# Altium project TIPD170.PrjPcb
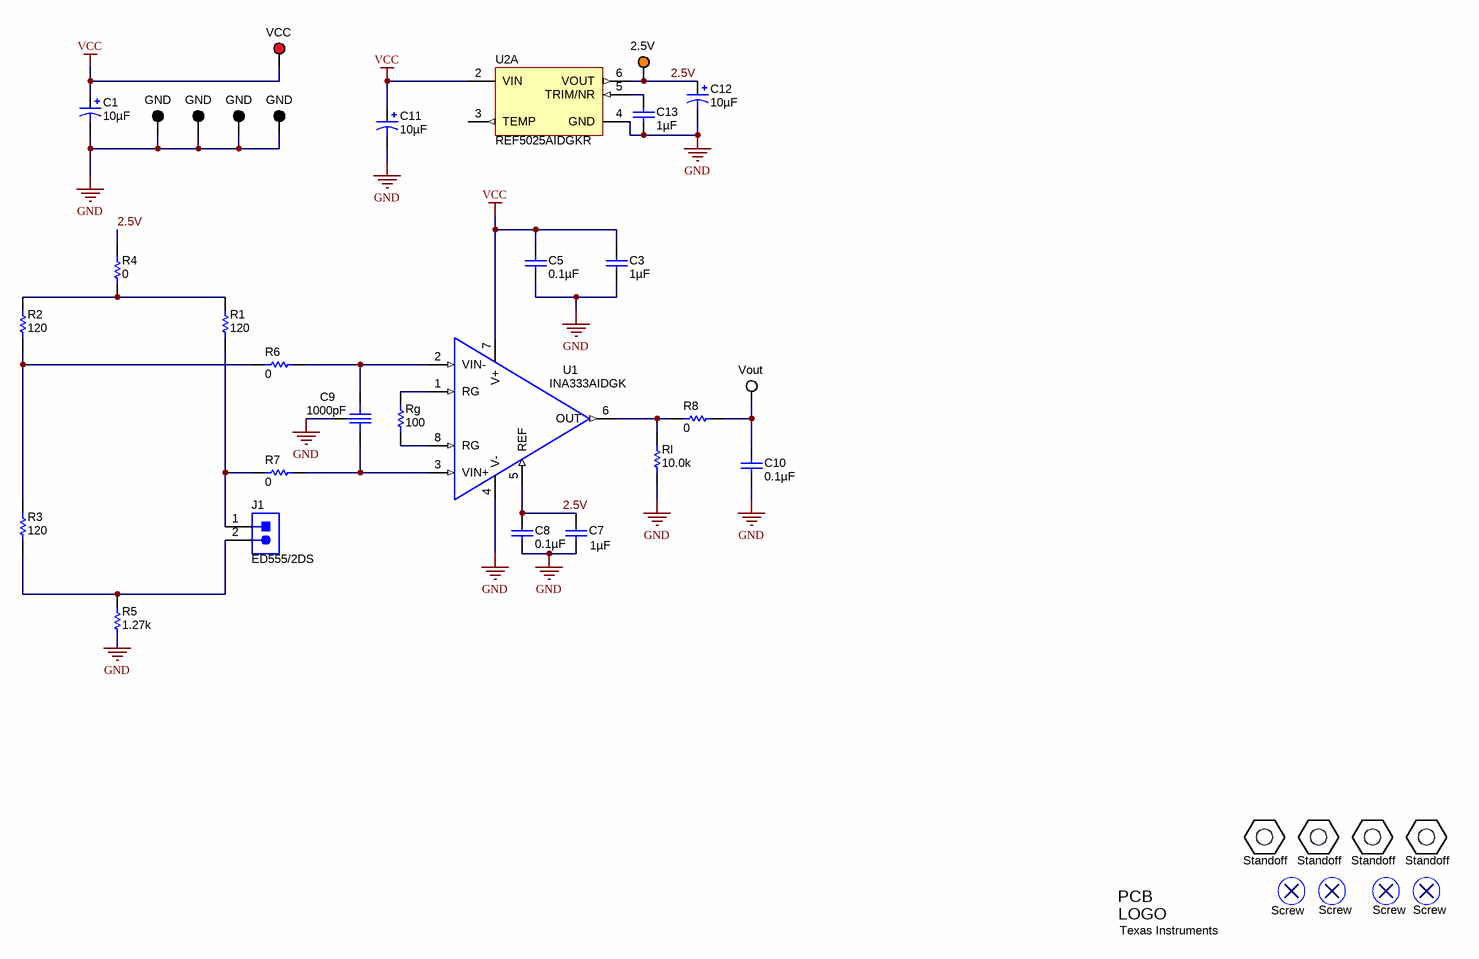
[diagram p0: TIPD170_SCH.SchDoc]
CopyrightYear: 2015; PRJ_Customer: TI Precision Designs; PRJ_Title: Strain Gauge in a Bridge Configuration Reference Design; SCH_Rev: 2; TechSupport: http://www.ti.com/support
1 sheet, 39 parts. Net scope: global (net labels, ports and power ports of the same name join across sheets).
Board file: TIPD170_PCB.PcbDoc

## Sheet TIPD170_SCH.SchDoc: TIPD170
size B; Date: Not shown in title block; ApprovedBy: Not shown in title block; CheckedBy: Not shown in title block; Author: Not shown in title block; CompanyName: Not shown in title block; DrawnBy: Not shown in title block; Engineer: Not shown in title block; Organization: Not shown in title block; Address1: Not shown in title block; Address2: Not shown in title block; Address3: Not shown in title block; Address4: Not shown in title block; DocumentNumber: 1; Revision: Use project parameter SCH_Rev; SheetNumber: 1; SheetTotal: 1; PageSetup: Record=PageOptions¦CenterHorizontal=True¦CenterVertical=True¦PrintScale=0.72¦XCorrection=1.00¦YCorrection=1.00¦PrintKind=0¦BorderSize=5000000¦LeftOffset=0¦BottomOffset=0¦Orientation=2¦PaperLength=1000¦PaperWidth=1000¦Scale=100¦PaperSource=15¦PrintQuality=600¦MediaType=1¦DitherType=10¦PaperKind=Letter¦PrintScaleMode=1

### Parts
C1  ValueDisplayed: 10µF  [3528-21]  (hidden comment: TPSB106M020R1000)
C3  ValueDisplayed: 1µF  [0603]  (hidden comment: GRM188R71E105KA12D)
C5  ValueDisplayed: 0.1µF  [0603]  (hidden comment: 0603YC104JAT2A)
C7  ValueDisplayed: 1µF  [0603]  (hidden comment: GRM188R71E105KA12D)
C8  ValueDisplayed: 0.1µF  [0603]  (hidden comment: 0603YC104JAT2A)
C9  ValueDisplayed: 1000pF  [X2Y_0603]  (hidden comment: CX0603MRX7R0BB102)
C10  ValueDisplayed: 0.1µF  [0603]  (hidden comment: 0603YC104JAT2A)
C11  ValueDisplayed: 10µF  [3528-21]  (hidden comment: TPSB106M020R1000)
C12  ValueDisplayed: 10µF  [3528-21]  (hidden comment: TPSB106M020R1000)
C13  ValueDisplayed: 1µF  [0603]  (hidden comment: GRM188R71E105KA12D)
J1  ED555/2DS  [TERM_BLK_ED555-2DS]
Logo1  Texas Instruments  [TI_Symbol_Overlay_Small]  (no BOM)
R1  ValueDisplayed: 120  [0603]  (hidden comment: RG1608P-121-B-T5)
R2  ValueDisplayed: 120  [0603]  (hidden comment: RG1608P-121-B-T5)
R3  ValueDisplayed: 120  [0603]  (hidden comment: RG1608P-121-B-T5)
R4  ValueDisplayed: 0  [0603]  (hidden comment: CRCW06030000Z0EA)
R5  ValueDisplayed: 1.27k  [0603]  (hidden comment: CRCW06031K27FKEA)
R6  ValueDisplayed: 0  [0603]  (hidden comment: CRCW06030000Z0EA)
R7  ValueDisplayed: 0  [0603]  (hidden comment: CRCW06030000Z0EA)
R8  ValueDisplayed: 0  [0603]  (hidden comment: CRCW06030000Z0EA)
Rg  value 100  [0603]  (hidden comment: RC0603FR-07100RL)
Rl  value 10.0k  [0603]  (hidden comment: CRCW060310K0FKEA)
TP1  VCC  [Keystone5005]
TP2  GND  [Keystone5006]
TP4  GND  [Keystone5006]
TP5  GND  [Keystone5006]
TP6  GND  [Keystone5006]
TP7  2.5V  [Keystone5008]
TP8  Vout  [Keystone5007]
U1  INA333AIDGK  [DGK0008A_N]
U2  REF5025AIDGKR  [DGK0008A_N]  (part A of 2)
U90  Standoff  [STANDOFF HEX 4-40THR ALUM 1"L]
U91  Standoff  [STANDOFF HEX 4-40THR ALUM 1"L]
U92  Standoff  [STANDOFF HEX 4-40THR ALUM 1"L]
U93  Standoff  [STANDOFF HEX 4-40THR ALUM 1"L]
U94  Screw  (mechanical)
U95  Screw  (mechanical)
U96  Screw  (mechanical)
U97  Screw  (mechanical)

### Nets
GND: C1.2(-) C3.2 C5.2 C7.2 C8.2 C9.3 C10.2 C11.2(-) C12.2(-) C13.2 R5.1 Rl.1 TP2.1 TP4.1 TP5.1 TP6.1 U1.4(V-) U2.4(GND)
VCC: C1.1(+) C3.1 C5.1 C11.1(+) TP1.1 U1.7(V+) U2.2(VIN)
2.5V: C7.1 C8.1 C12.1(+) R4.2 TP7.1 U1.5(REF) U2.6(VOUT)
NetC9_1: C9.1 R6.1 U1.2(VIN-)
NetC9_2: C9.2 R7.1 U1.3(VIN+)
NetC10_1: C10.1 R8.2 TP8.1
NetC13_1: C13.1 U2.5(TRIM/NR)
NetJ1_1: J1.1 R1.1 R7.2
NetJ1_2: J1.2 R3.1 R5.2
NetR1_2: R1.2 R2.2 R4.1
NetR2_1: R2.1 R3.2 R6.2
NetR8_1: R8.1 Rl.2 U1.6(OUT)
NetRg_1: Rg.1 U1.8(RG)
NetRg_2: Rg.2 U1.1(RG)

Not connected (* = marked no-connect by the designer): U2 3(TEMP)

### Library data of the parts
C1 C11 C12 = TPSB106M020R1000: CAP, TANT, 10uF, 20V, +/-20%, 1 ohm, 3528-21 SMD; Manufacturer: AVX; Polarized: Y; CompType: Capacitor; U/M: EA; Cap_F: 0.00001; Tolerance_%: 20; Value1: 1 ohm; ESR_Ohm: 1; IRMS_A: 0.262; TaMin_C: -55; TaMax_C: 125; Cap_Case: B
C3 C7 C13 = GRM188R71E105KA12D: CAP, CERM, 1uF, 25V, +/-10%, X7R, 0603; Manufacturer: MuRata; Polarized: N; CompType: Capacitor; U/M: EA; Cap_F: 0.000001; Tolerance_%: 10; Value1: Unknown; VDC_V: 25; TaMin_C: -55; TaMax_C: 125
C5 C8 C10 = 0603YC104JAT2A: CAP, CERM, 0.1uF, 16V, +/-5%, X7R, 0603; Manufacturer: AVX; Polarized: N; CompType: Capacitor; U/M: EA; Cap_F: 0.0000001; Tolerance_%: 5; ESR_Ohm: 0.039; Value1: 0.039 ohm; VDC_V: 16; TaMin_C: -55; TaMax_C: 125
C9 = CX0603MRX7R0BB102: CAP, CERM, 1000 pF, 100 V, +/- 20%, X7R, 0603; Manufacturer: Yageo America; SymbolCreator: a0411947; CompType: Capacitor; U/M: EA; Cap_F: 0.000000001; Value: 1000pF; Tolerance_%: 20; Value1: Unknown; VDC_V: 100; Value2: 100V; TaMin_C: -55; TaMax_C: 125; Polarized: N; Cap_Case: 0603
J1 = ED555/2DS: Terminal Block, 6A, 3.5mm Pitch, 2-Pos, TH; Manufacturer: On-Shore Technology; SymbolCreator: a0412235; CompType: Connector; U/M: EA
Logo1 = TI_Logo: Texas Instrument Corporate Signature; SymbolCreator: codlsc
R1-R3 = RG1608P-121-B-T5: RES, 120, 0.1%, 0.1 W, 0603; Manufacturer: Susumu Co Ltd; CompType: Resistor; Value: 120; Value_Code: 120R; Tolerance_%: 0.1; Value2: 0.1W; VDC_V: 75; TempCo: 25 ppm/C; EIA_Code: E192; U/M: EA
R4 R6-R8 = CRCW06030000Z0EA: RES, 0, 5%, 0.1 W, 0603; Manufacturer: Vishay-Dale; CompType: Resistor; Value: 0; Value_Code: 0000; Tolerance_%: 5; Power_W: 0.1; Value2: 0.1W; VDC_V: 75; TempCo: 200 ppm/C; EIA_Code: E24; U/M: EA; AEC Category: Q200
R5 = CRCW06031K27FKEA: RES, 1.27 k, 1%, 0.1 W, 0603; Manufacturer: Vishay-Dale; CompType: Resistor; Value: 1.27k; Res_ohm: 1270; Value_Code: 1k27; Tolerance_%: 1; Power_W: 0.1; Value2: 0.1W; VDC_V: 75; TempCo: 100 ppm/C; EIA_Code: E96; U/M: EA; AEC Category: Q200
Rg = RC0603FR-07100RL: RES, 100 ohm, 1%, 0.1W, 0603; Manufacturer: Yageo America; CompType: Resistor; Value_Code: 100R; Tolerance_%: 1; Power_W: 0.1; VDC_V: 150; TempCo: 200 ppm/C; EIA_Code: E96; U/M: EA
Rl = CRCW060310K0FKEA: RES, 10.0k ohm, 1%, 0.1W, 0603; Manufacturer: Vishay-Dale; CompType: Resistor; Res_ohm: 10000; Value_Code: 10k0; Tolerance_%: 1; Power_W: 0.1; VDC_V: 75; TempCo: 100 ppm/C; EIA_Code: E96; U/M: EA
TP1 = 5005: Test Point, TH, Compact, Red; Manufacturer: Keystone; Alternate Manufacturer: Any; Alternate PartNumber: Equivalent; CompType: Test Point Loop; U/M: EA
TP2 TP4-TP6 = 5006: Test Point, TH, Compact, Black; Manufacturer: Keystone; Alternate Manufacturer: Any; Alternate PartNumber: Equivalent; CompType: Test Point Loop; U/M: EA
TP7 = 5008: Test Point, Compact, Orange, TH; Manufacturer: Keystone; CompType: Test Point Loop; U/M: EA
TP8 = 5007: Test Point, Compact, White, TH; Manufacturer: Keystone; CompType: Test Point Loop; U/M: EA
U1 = INA333AIDGK: Micro-Power (50mA), Zerø-Drift, Rail-to-Rail Out Instrumentation Amplifier; Manufacturer: Texas Instruments; SymbolCreator: a0799628; CompType: IC; U/M: EA
U2 = REF5025AIDGKR: Low Noise, Very Low Drift, Precision Voltage Reference, -40 to 125 degC, 8-pin MSOP(DGK), Green (RoHS & no Sb/Br); Manufacturer: Texas Instruments; Alternate Manufacturer: None; Alternate PartNumber: Equivalent; Initial Accuracy @ 25/deg C(%): 0.05; Iout/Iz(Max)(mA): 10; Iq(Max)(uA): 1000; Rating: Military; SubFamily: Series Voltage Reference; Temp Coeff(Max)(ppm/ degree C): 3; VI(Max)(V): 18; VI(Min)(V): 2.7; VO(V): 2.5
U90-U93 = Standoff, 1", 4-40, Alum, F-F: STANDOFF HEX 4-40THR ALUM 1"L; Manufacturer: Keystone; PartNumber: 2205; SymbolVersion: use current date i.e. 2008-05-20; SymbolCreator: Use LDAP id; CompType: Used in some BOM reports.  Useful for finding later.; U/M: EA, IN, or GM
U94-U97 = Machine Screw, 4-40, 0.25": MACHINE SCREW PAN PHILLIPS 4-40; Manufacturer: B&F Fastener Supply; PartNumber: PMSSS 440 0025 PH; SymbolVersion: use current date i.e. 2008-05-20; SymbolCreator: Use LDAP id; CompType: Mechanical; U/M: EA, IN, or GM

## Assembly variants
001: not fitted C9 C10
